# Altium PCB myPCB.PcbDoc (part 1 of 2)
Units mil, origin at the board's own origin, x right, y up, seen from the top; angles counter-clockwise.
Board outline 3914 x 3499.3 mil, 2 copper layers (Top Layer, Bottom Layer); 61 components, 196 nets, 504 pads, 76 vias.
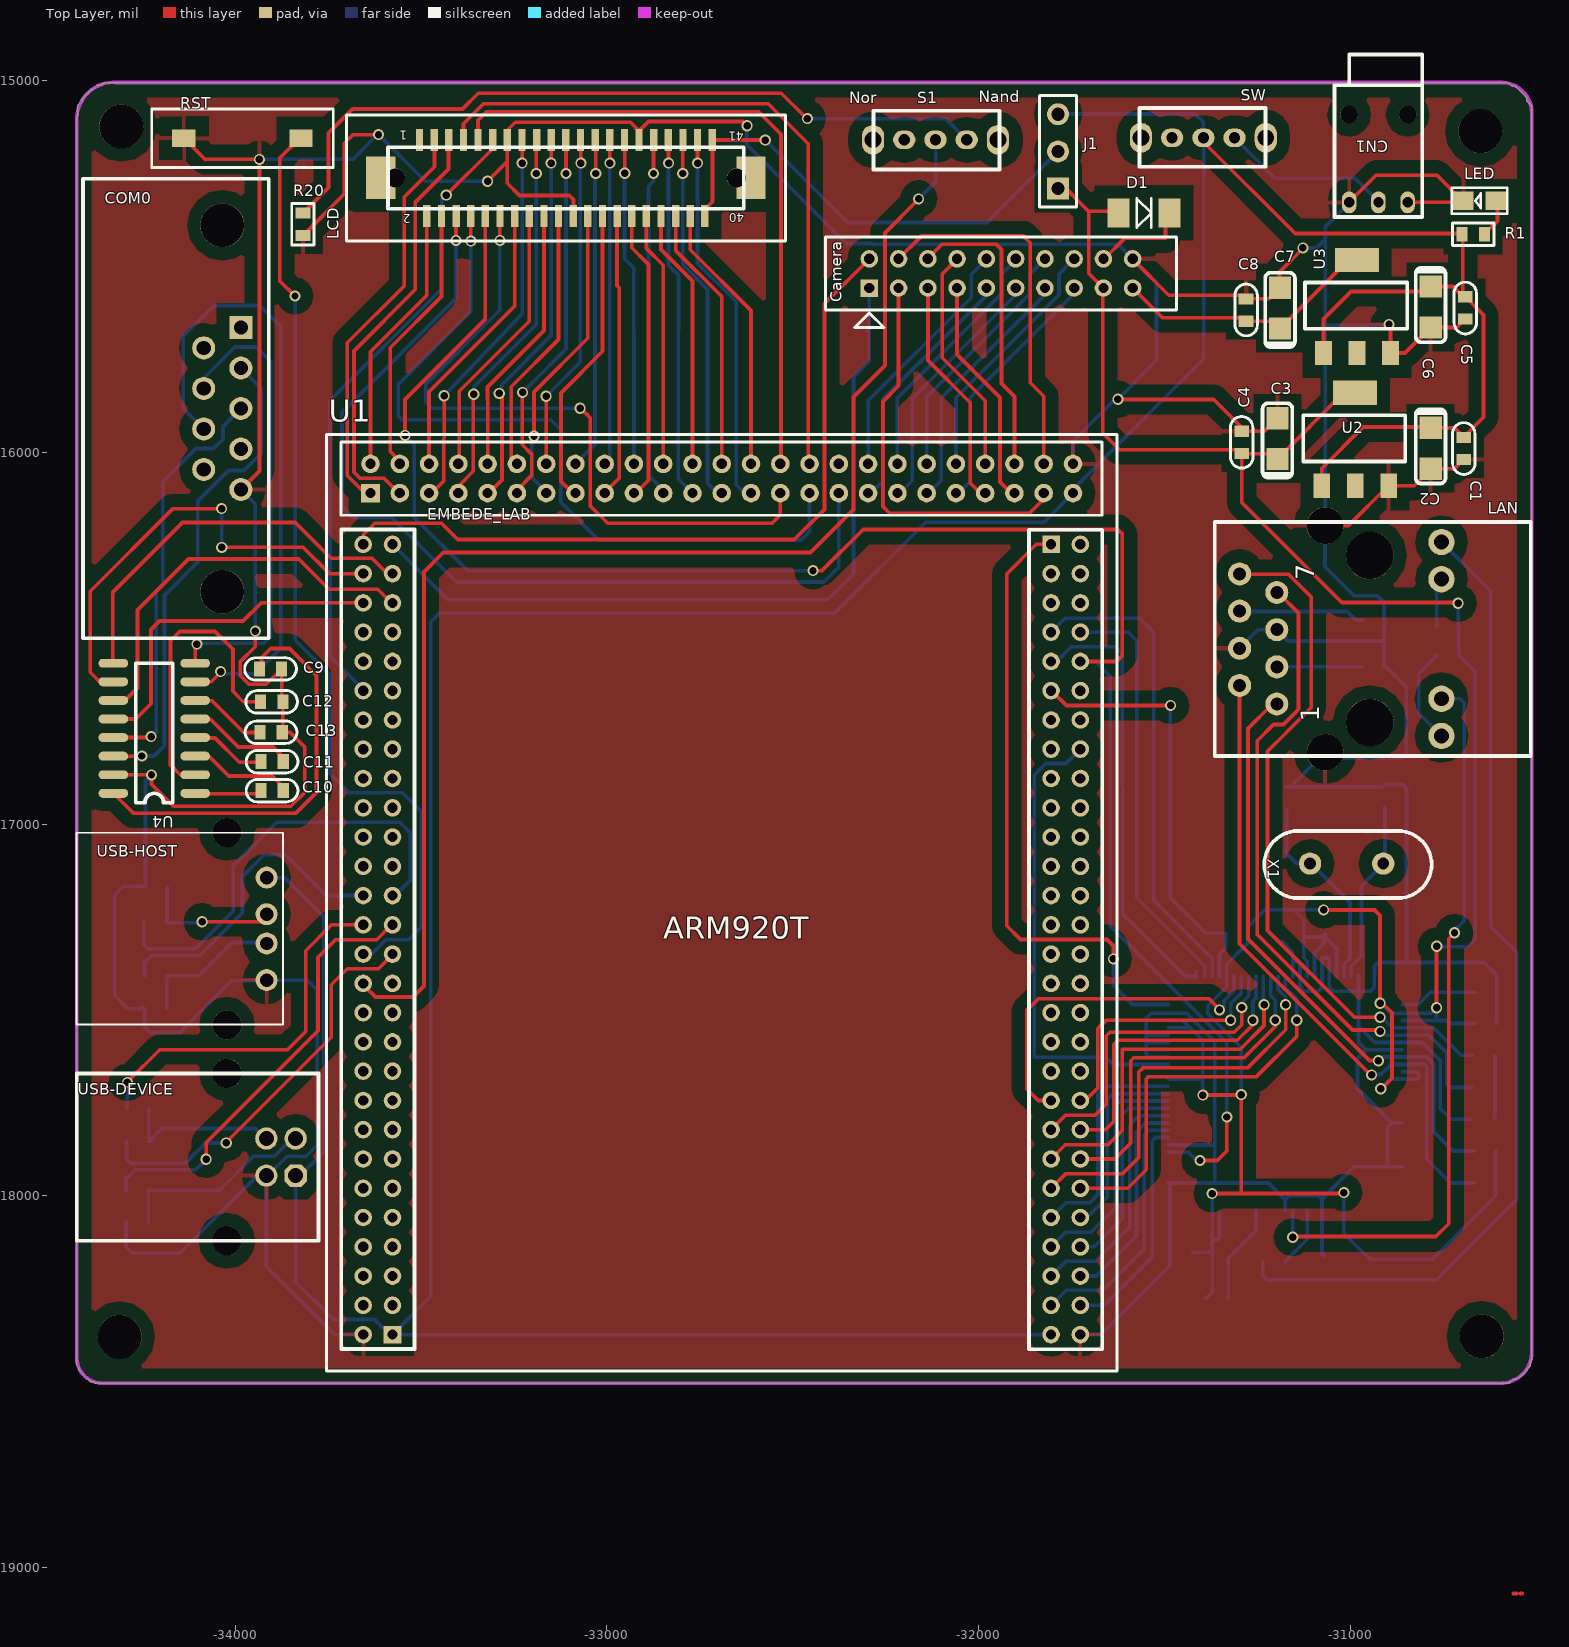
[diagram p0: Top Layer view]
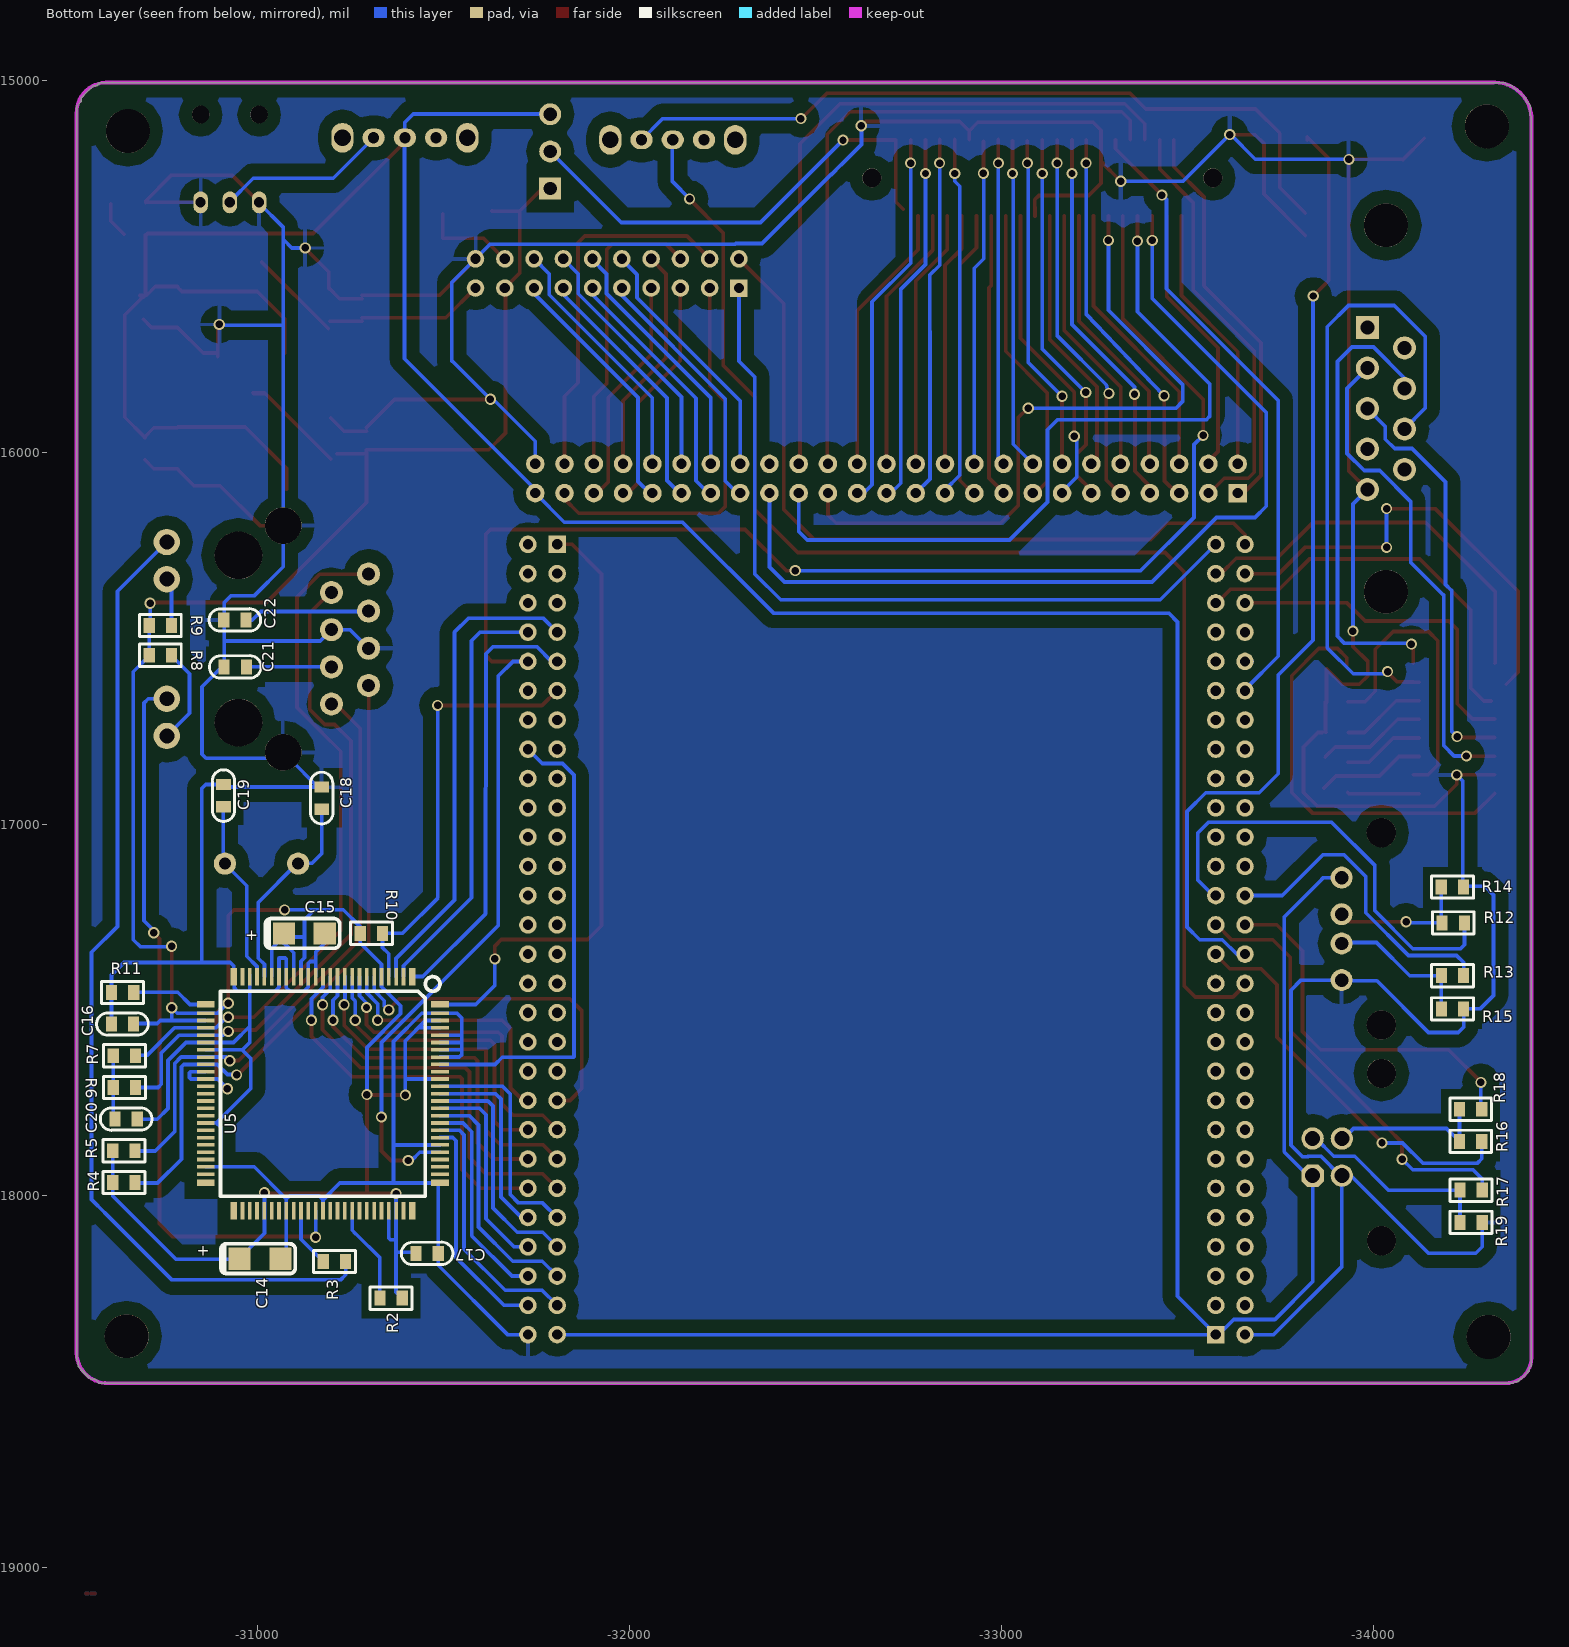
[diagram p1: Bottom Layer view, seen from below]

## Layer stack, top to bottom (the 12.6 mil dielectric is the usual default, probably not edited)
Top Layer: signal copper 1.4
Dielectric: dielectric 12.6, FR-4, Dk 4.8
Bottom Layer: signal copper 1.4

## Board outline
-30598.21,-18504.31 -30572.65,-18504.31 -30571.02,-18502.67 -30562.69,-18494.34 -30553.67,-18494.34 -30551.36,-18494.34 -30545.11,-18488.1 -30524.99,-18467.98 -30524.99,-18467.05 -30516.44,-18458.49 -30516.44,-18446.47 -30512.05,-18442.08 -30512.05,-18422.74 -30512.05,-18388.93 -30512,-18388.88 -30512,-15095.34 -30512,-15068.86 -30518.89,-15061.97 -30525.01,-15055.85 -30525.01,-15050.31 -30525.01,-15045.91 -30539.91,-15031.01 -30556.92,-15013.99 -30566.29,-15013.99 -30574.32,-15005.97 -30585.98,-15005.97 -30608.9,-15005.97 -30609.87,-15005 -30610.4,-15005.53 -34345.49,-15005.53 -34353.67,-15005.53 -34356.4,-15008.26 -34361.19,-15013.05 -34366.96,-15013.05 -34371.71,-15013.05 -34378.24,-15019.58 -34381.56,-15022.9 -34386.55,-15022.9 -34386.55,-15023.61 -34399.18,-15036.24 -34410.98,-15048.04 -34410.98,-15052.67 -34410.98,-15054.75 -34419.3,-15063.07 -34423,-15066.77 -34423,-15083.89 -34423,-15094 -34426,-15097 -34426,-18436.3 -34426,-18456.5 -34420.33,-18462.17 -34420.33,-18469.44 -34409.14,-18480.64 -34389.27,-18500.51 -34380.6,-18500.51 -34376.8,-18504.31 -34356.93,-18504.31 -34282.37,-18504.31 -30598.21,-18504.31

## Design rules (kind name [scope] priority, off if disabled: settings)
Clearance [All] p1: gap=8
ComponentClearance [All] p1: gap=8 collisioncheckmode=3 verticalgap=10 showdistances=FALSE
FabricationTestpoint [(IsPad And (OnTopLayer Or OnBottomLayer))] p1: side=3 testpointundercomponent=TRUE minsize=40 maxsize=100 preferedsize=60 minholesize=0 maxholesize=40 preferedholesize=32 testpointgrid=1 allowsidetop=TRUE allowsidebottom=TRUE usegrid=TRUE gridtolerance=0.01
PolygonConnect [All] p1: connectstyle=Relief reliefconductorwidth=10 reliefentries=4 polygonreliefangle="90 Angle"
RoutingLayers [All] p1: top layer_v5=FALSE bottom layer_v5=FALSE
RoutingVias [All] p1: holewidth=20 width=30 viastyle="Through Hole" minholewidth=20 minwidth=30 maxholewidth=20 maxwidth=30
SMDNeckDown [All] p1: percent=110.000
SilkscreenOverComponentPads [All] p1: minsilkscreentomaskgap=10
SolderMaskExpansion [All] p1: expansion=4
Width [All] p1: maxlimit=12 minlimit=10 preferedwidth=11
24 further rules are at their usual default settings.

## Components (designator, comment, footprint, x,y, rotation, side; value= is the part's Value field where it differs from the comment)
C1 "Cap" 0603A -30696,-15960 r270 top
C2 "Cap2" C3216 -30784,-15934 r180 top
C3 "Cap2" C3216 -31196,-16018 r0 top
C4 "Cap" 0603A -31291,-16003 r90 top
C5 "Cap" 0603A -30692,-15582 r270 top
C6 "Cap2" C3216 -30784,-15554 r180 top
C7 "Cap2" C3216 -31189,-15667 r0 top
C8 "Cap" 0603A -31279,-15647 r90 top
C9 "Cap Semi" 0603A -33934.71,-16584 r0 top
C10 "Cap Semi" 0603A -33871,-16909 r180 top
C11 "Cap Semi" 0603A -33871,-16831 r180 top
C12 "Cap Semi" 0603A -33872,-16670 r180 top
C13 "Cap Semi" 0603A -33873.71,-16752 r180 top
C14 "10uF" C3216 -30950.56,-18169.35 r270 bottom
C15 "10uF" C3216 -31070,-17294.45 r270 bottom
C16 "0.1uF" 0603A -30665.41,-17536.83 r0 bottom
C17 "0.1uF" 0603A -31425.3,-18156.28 r180 bottom
C18 "22p" 0603A -31172.8,-16959.99 r90 bottom
C19 "22p" 0603A -30908.63,-16953.39 r90 bottom
C20 "0.1u" 0603A -30615.54,-17794.85 r180 bottom
C21 "104" 0603A -30968.89,-16576.09 r0 bottom
C22 "104" 0603A -30967.82,-16449.79 r0 bottom
Camera "CON20" IDC20SS -32294,-15558 r180 top locked
CN1 "DC_JACK" DC25 -30924,-15013 r180 top
COM0 "" DB9RA/M -33984.31,-15664.54 r90 top locked
D1 "1N4148" D1206 -31624.53,-15355.89 r0 top
J1 "" HDR1X3 -31786.24,-15290.62 r90 top
LAN "HR911103A" HR911103A -30948,-16501.53 r270 top
LCD "LCD41P" DF9B-41P-1V2 -32651,-15262 r180 top locked
LED "POWER" LED -30609,-15323 r180 top
R1 "500" 0603R -30639,-15413 r180 top
R2 "4.7K" 0603R -31327.63,-18276.01 r180 bottom
R3 "0" 0603R -31236.4,-18176.39 r0 bottom
R4 "50" 0603R -30670.01,-17963.9 r0 bottom
R5 "50" 0603R -30670.01,-17878.7 r0 bottom
R6 "50" 0603R -30610.54,-17709.1 r180 bottom
R7 "50" 0603R -30610.54,-17623.9 r180 bottom
R8 "1K" 0603R -30768,-16545.53 r0 bottom
R9 "1K" 0603R -30768,-16465.53 r0 bottom
R10 "4.7K" 0603R -31274.89,-17294.5 r180 bottom
R11 "6.8K" 0603R -30605.39,-17453.51 r180 bottom
R12 "22" 0603R -34185.16,-17266.39 r180 bottom
R13 "22" 0603R -34183.22,-17408.36 r180 bottom
R14 "15K" 0603R -34183,-17170 r180 bottom
R15 "15K" 0603R -34183.22,-17497.73 r180 bottom
R16 "1.5K" 0603R -34293.02,-17853.34 r0 bottom
R17 "22" 0603R -34294.11,-17984.61 r0 bottom
R18 "22" 0603R -34293.02,-17766.94 r0 bottom
R19 "470K" 0603R -34233.06,-18072.18 r180 bottom
R20 "1K" 0603R -33818.13,-15356.13 r270 top
RST "SW-PB" RST -33980.3,-15154.99 r180 top
S1 "CON5" PCBComponent_1 -32280.01,-15139.29 r0 top
SW "CON5" PCBComponent_1 -31231.36,-15173.89 r180 top
U1 "Micro2440" MICRO2440 -33636.3,-16109.77 r270 top locked
U2 "LM1117" SOT223S -30897,-16090 r90 top
U3 "LM1117" SOT223S -30892,-15733 r90 top
U4 "MAX3232SOP" SSOP16 -34108,-16917 r270 top locked
U5 "DM9000" QFP100 -31415,-17410 r0 bottom
USB-DEVICE "USB Port B type" USB-B -33837.52,-17945.77 r270 top locked
USB-HOST "USB Port A type" USB-A -33915.91,-17143.88 r270 top
X1 "25M" OSC2PR-1 -31108,-17106 r0 top

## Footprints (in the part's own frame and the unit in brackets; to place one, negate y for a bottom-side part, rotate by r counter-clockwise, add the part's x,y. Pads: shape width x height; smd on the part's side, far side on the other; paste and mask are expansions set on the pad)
0603A [mil]
  rect 30x40 smd: 1(-0.26,1.21) 2(59.74,1.21)
  silkscreen extent -40,-29 99,31
0603R [mil]
  rect 30x40 smd: 1(0.47,0.42) 2(60.47,0.42)
  silkscreen extent -26,-30 87,30
C3216 [mil]
  rect 60x60 smd: 1(0,0) 2(0,110)
  silkscreen extent -40,-50 40,150
D1206 [mm]
  rect 1.5x2 smd: 1(0.015,-0.01) 2(3.515,-0.01)
  silkscreen extent 1.26,-1.01 2.26,0.99
DB9RA/M [mil]
  rect 62x62 hole 38: 1(0.38,0.31)
  round 62 hole 38: 2(-108.62,0.31) 3(-217.62,0.31) 4(-326.62,0.31) 5(-435.62,0.31) 6(-54.62,100.31) 7(-163.62,100.31) 8(-272.62,100.31) 9(-381.62,100.31)
  round 118.11 hole 118.11: ""(-710.62,50.31) ""(275.38,50.31)
  silkscreen extent -836,-75 400,425
DC25 [mm]
  oval 1x1.5 hole 0.7: 1(2.012,7.989) 2(0.012,7.989) 3(-1.988,7.989)
  round 1.2 hole 1.2: A(-1.988,1.989) B(2.012,1.989)
  silkscreen extent -2.99,-2.11 3.01,8.99
DF9B-41P-1V2 [mm]
  rect 0.5x1.5 smd: 1(21.667,-2.605) 2(21.167,2.595) 3(20.667,-2.605) 4(20.167,2.595) 5(19.667,-2.605) 6(19.167,2.595) 7(18.667,-2.605) 8(18.167,2.595) 9(17.667,-2.605) 10(17.167,2.595) 11(16.667,-2.605) 12(16.167,2.595) 13(15.667,-2.605) 14(15.167,2.595) 15(14.667,-2.605) 16(14.167,2.595) 17(13.667,-2.605) 18(13.167,2.595) 19(12.667,-2.605) 20(12.167,2.595) 21(11.667,-2.605) 22(11.167,2.595) 23(10.667,-2.605) 24(10.167,2.595) 25(9.667,-2.605) 26(9.167,2.595) 27(8.667,-2.605) 28(8.167,2.595) 29(7.667,-2.605) 30(7.167,2.595) 31(6.667,-2.605) 32(6.167,2.595) 33(5.667,-2.605) 34(5.167,2.595) 35(4.667,-2.605) 36(4.167,2.595) 37(3.667,-2.605) 38(3.167,2.595) 39(2.667,-2.605) 40(2.167,2.595) 41(1.667,-2.605)
  round 1.3 hole 1.3: A(0.017,-0.005) B(23.317,-0.005)
  rect 2x2.9 smd: C(-0.983,-0.005) D(24.317,-0.005)
  silkscreen extent -3.33,-4.31 26.67,4.3
HDR1X3 [mm] "Connector; Header; 3 Position"
  rect 1.5x1.5 hole 0.9: 1(0,0)
  round 1.5 hole 0.9: 2(2.54,0) 3(5.08,0)
  silkscreen extent -1.27,-1.27 6.35,1.27
HR911103A [mil]
  round 62 hole 35: 1(175.67,-249.76) 2(125.67,-349.76) 3(75.67,-249.76) 4(25.67,-349.76) 5(-24.33,-249.76) 6(-74.33,-349.76) 7(-124.33,-249.76) 8(-174.33,-349.76)
  round 70.87 hole 40.16: 9(261.5,193.16) 10(161.5,193.16) 11(-160.16,193.16) 12(-260.16,193.16)
  round 98.42 hole 98.43: A(305.59,-119.83) B(-304.25,-119.83)
  round 127.95 hole 127.95: C(-224.33,0.24) D(225.67,0.24)
  silkscreen extent -314,-416 316,433
IDC20SS [mm]
  rect 1.2x1.2 hole 0.7: 1(0.002,0.003)
  round 1.2 hole 0.7: 2(0.002,-1.997) 3(-1.998,0.003) 4(-1.998,-1.997) 5(-3.998,0.003) 6(-3.998,-1.997) 7(-5.998,0.003) 8(-5.998,-1.997) 9(-7.998,0.003) 10(-7.998,-1.997) 11(-9.998,0.003) 12(-9.998,-1.997) 13(-11.998,0.003) 14(-11.998,-1.997) 15(-13.998,0.003) 16(-13.998,-1.997) 17(-15.998,0.003) 18(-15.998,-1.997) 19(-17.998,0.003) 20(-17.998,-1.997)
  silkscreen extent -21,-3.5 3,2.7
LED [mil]
  rect 55.12x50 smd: 1(-0.13,0.5) 2(86.87,0.5)
  silkscreen extent -32,-35 118,36
MICRO2440 [mm]
  rect 1.2x1.2 hole 0.7: PA1(57.501,1.512) PC1(3.501,46.512)
  round 1.2 hole 0.7: PA2(57.501,-0.488) PA3(55.501,1.512) PA4(55.501,-0.488) PA5(53.501,1.512) PA6(53.501,-0.488) PA7(51.501,1.512) PA8(51.501,-0.488) PA9(49.501,1.512) PA10(49.501,-0.488) PA11(47.501,1.512) PA12(47.501,-0.488) PA13(45.501,1.512) PA14(45.501,-0.488) PA15(43.501,1.512) PA16(43.501,-0.488) PA17(41.501,1.512) PA18(41.501,-0.488) PA19(39.501,1.512) PA20(39.501,-0.488) PA21(37.501,1.512) PA22(37.501,-0.488) PA23(35.501,1.512) PA24(35.501,-0.488) PA25(33.501,1.512) PA26(33.501,-0.488) PA27(31.501,1.512) PA28(31.501,-0.488) PA29(29.501,1.512) PA30(29.501,-0.488) PA31(27.501,1.512) PA32(27.501,-0.488) PA33(25.501,1.512) PA34(25.501,-0.488) PA35(23.501,1.512) PA36(23.501,-0.488) PA37(21.501,1.512) PA38(21.501,-0.488) PA39(19.501,1.512) PA40(19.501,-0.488) PA41(17.501,1.512) PA42(17.501,-0.488) PA43(15.501,1.512) PA44(15.501,-0.488) PA45(13.501,1.512) PA46(13.501,-0.488) PA47(11.501,1.512) PA48(11.501,-0.488) PA49(9.501,1.512) PA50(9.501,-0.488) PA51(7.501,1.512) PA52(7.501,-0.488) PA53(5.501,1.512) PA54(5.501,-0.488) PA55(3.501,1.512) PA56(3.501,-0.488) PC2(3.501,48.512) PC3(5.501,46.512) PC4(5.501,48.512) PC5(7.501,46.512) PC6(7.501,48.512) PC7(9.501,46.512) PC8(9.501,48.512) PC9(11.501,46.512) PC10(11.501,48.512) PC11(13.501,46.512) PC12(13.501,48.512) PC13(15.501,46.512) PC14(15.501,48.512) PC15(17.501,46.512) PC16(17.501,48.512) PC17(19.501,46.512) PC18(19.501,48.512) PC19(21.501,46.512) PC20(21.501,48.512) PC21(23.501,46.512) PC22(23.501,48.512) PC23(25.501,46.512) PC24(25.501,48.512) PC25(27.501,46.512) PC26(27.501,48.512) PC27(29.501,46.512) PC28(29.501,48.512) PC29(31.501,46.512) PC30(31.501,48.512) PC31(33.501,46.512) PC32(33.501,48.512) PC33(35.501,46.512) PC34(35.501,48.512) PC35(37.501,46.512) PC36(37.501,48.512) PC37(39.501,46.512) PC38(39.501,48.512) PC39(41.501,46.512) PC40(41.501,48.512) PC41(43.501,46.512) PC42(43.501,48.512) PC43(45.501,46.512) PC44(45.501,48.512) PC45(47.501,46.512) PC46(47.501,48.512) PC47(49.501,46.512) PC48(49.501,48.512) PC49(51.501,46.512) PC50(51.501,48.512) PC51(53.501,46.512) PC52(53.501,48.512) PC53(55.501,46.512) PC54(55.501,48.512) PC55(57.501,46.512) PC56(57.501,48.512)
  rect 1.27x1.27 hole 0.7: PB1(0.001,0.012)
  round 1.27 hole 0.7: PB2(-1.999,0.012) PB3(0.001,2.012) PB4(-1.999,2.012) PB5(0.001,4.012) PB6(-1.999,4.012) PB7(0.001,6.012) PB8(-1.999,6.012) PB9(0.001,8.012) PB10(-1.999,8.012) PB11(0.001,10.012) PB12(-1.999,10.012) PB13(0.001,12.012) PB14(-1.999,12.012) PB15(0.001,14.012) PB16(-1.999,14.012) PB17(0.001,16.012) PB18(-1.999,16.012) PB19(0.001,18.012) PB20(-1.999,18.012) PB21(0.001,20.012) PB22(-1.999,20.012) PB23(0.001,22.012) PB24(-1.999,22.012) PB25(0.001,24.012) PB26(-1.999,24.012) PB27(0.001,26.012) PB28(-1.999,26.012) PB29(0.001,28.012) PB30(-1.999,28.012) PB31(0.001,30.012) PB32(-1.999,30.012) PB33(0.001,32.012) PB34(-1.999,32.012) PB35(0.001,34.012) PB36(-1.999,34.012) PB37(0.001,36.012) PB38(-1.999,36.012) PB39(0.001,38.012) PB40(-1.999,38.012) PB41(0.001,40.012) PB42(-1.999,40.012) PB43(0.001,42.012) PB44(-1.999,42.012) PB45(0.001,44.012) PB46(-1.999,44.012) PB47(0.001,46.012) PB48(-1.999,46.012) PB49(0.001,48.012) PB50(-1.999,48.012)
  silkscreen extent -4,-2.99 60,51.01
OSC2PR-1 [mil]
  round 60 hole 32: 1(-0.31,-0.47) 2(196.69,-0.47)
  silkscreen extent -123,-93 327,87
PCBComponent_1 [mil]
  oval 60x80 hole 45: 1(-4,-20) 5(332,-20)
  oval 60x50 hole 30: 2(80,-20) 3(164,-20) 4(248,-20)
  silkscreen extent -3,-100 336,58
QFP100 [mm]
  rect 0.45x1.2 smd: 1(-0.002,0.012) 25(12.198,0.012) 51(12.198,16.012) 75(-0.002,16.012)
  rect 0.25x1.2 smd: 2(0.598,0.012) 3(1.098,0.012) 4(1.598,0.012) 5(2.098,0.012) 6(2.598,0.012) 7(3.098,0.012) 8(3.598,0.012) 9(4.098,0.012) 10(4.598,0.012) 11(5.098,0.012) 12(5.598,0.012) 13(6.098,0.012) 14(6.598,0.012) 15(7.098,0.012) 16(7.598,0.012) 17(8.098,0.012) 18(8.598,0.012) 19(9.098,0.012) 20(9.598,0.012) 21(10.098,0.012) 22(10.598,0.012) 23(11.098,0.012) 24(11.598,0.012) 52(11.598,16.012) 53(11.098,16.012) 54(10.598,16.012) 55(10.098,16.012) 56(9.598,16.012) 57(9.098,16.012) 58(8.598,16.012) 59(8.098,16.012) 60(7.598,16.012) 61(7.098,16.012) 62(6.598,16.012) 63(6.098,16.012) 64(5.598,16.012) 65(5.098,16.012) 66(4.598,16.012) 67(4.098,16.012) 68(3.598,16.012) 69(3.098,16.012) 70(2.598,16.012) 71(2.098,16.012) 72(1.598,16.012) 73(1.098,16.012) 74(0.598,16.012)
  rect 1.2x0.45 smd: 26(14.098,1.912) 50(14.098,14.112) 76(-1.902,14.112) 100(-1.902,1.912)
  rect 1.2x0.25 smd: 27(14.098,2.512) 28(14.098,3.012) 29(14.098,3.512) 30(14.098,4.012) 31(14.098,4.512) 32(14.098,5.012) 33(14.098,5.512) 34(14.098,6.012) 35(14.098,6.512) 36(14.098,7.012) 37(14.098,7.512) 38(14.098,8.012) 39(14.098,8.512) 40(14.098,9.012) 41(14.098,9.512) 42(14.098,10.012) 43(14.098,10.512) 44(14.098,11.012) 45(14.098,11.512) 46(14.098,12.012) 47(14.098,12.512) 48(14.098,13.012) 49(14.098,13.512) 77(-1.902,13.512) 78(-1.902,13.012) 79(-1.902,12.512) 80(-1.902,12.012) 81(-1.902,11.512) 82(-1.902,11.012) 83(-1.902,10.512) 84(-1.902,10.012) 85(-1.902,9.512) 86(-1.902,9.012) 87(-1.902,8.512) 88(-1.902,8.012) 89(-1.902,7.512) 90(-1.902,7.012) 91(-1.902,6.512) 92(-1.902,6.012) 93(-1.902,5.512) 94(-1.902,5.012) 95(-1.902,4.512) 96(-1.902,4.012) 97(-1.902,3.512) 98(-1.902,3.012) 99(-1.902,2.512)
  silkscreen extent -1.9,0.01 13.1,15.01
RST [mm]
  rect 1.6x1.2 smd: 1(-4,0) 2(4,0)
  silkscreen extent -6.2,-2 6.2,2
SOT223S [mil]
  rect 65x45 smd: 1(0,0) 2(0,90) 3(0,180)
  rect 65x118 smd: 4(250,90)
  silkscreen extent 65,-45 190,230
SSOP16 [mil]
  oval 24x80 smd: 1(0.44,0.31) 2(-49.56,0.31) 3(-99.56,0.31) 4(-149.56,0.31) 5(-199.56,0.31) 6(-249.56,0.31) 7(-299.56,0.31) 8(-349.56,0.31) 9(-349.56,-219.69) 10(-299.56,-219.69) 11(-249.56,-219.69) 12(-199.56,-219.69) 13(-149.56,-219.69) 14(-99.56,-219.69) 15(-49.56,-219.69) 16(0.44,-219.69)
  silkscreen extent -350,-160 25,-60
USB-A [mm]
  round 1.5 hole 0.92: 1(0.009,0.013) 2(2.509,0.013) 3(4.509,0.013) 4(7.009,0.013)
  round 2 hole 2: 5(10.079,-2.697) 6(-3.061,-2.697)
  silkscreen extent -3.06,-12.98 10.04,1.12
USB-B [mil]
  oct 60x60 hole 40: 1(0.24,0.17)
  round 60 hole 40: 2(-99.76,0.17) 3(-99.76,-78.57) 4(0.24,-78.57)
  round 78.74 hole 78.74: 5(175.24,-184.87) 6(-274.76,-184.87)
  silkscreen extent -275,-589 175,61

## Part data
C1 C2 C3 C4 C5 C6 C7 C8: "Capacitor"
C9 C10 C11 C12 C13: "Capacitor (Semiconductor SIM Model)"
C14 C15: library part ELECTRO1
C16 C17 C18 C19 C20: library part CAP
C21 C22: library part "CAP NP_0"
Camera S1 SW: "Connector"
CN1: library part CON3
COM0: library part "CONNECTOR DB9"
D1: library part DIODE
J1: library part "Header 3", "Header, 3-Pin"
LED: library part LED3, "Typical BLUE SiC LED"
R1 R8 R9 R20: library part RES1
R2 R3 R4 R5 R6 R7 R11: library part RES2
R10: library part R_0
R12 R13 R14 R15 R16 R17 R18 R19: library part RESISTOR_2
RST: "Switch"
U1 U4: library part Component_1
USB-DEVICE USB-HOST: library part USBPORT
X1: library part CRYSTAL

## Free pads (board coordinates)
  round 118.11 hole 118.11: 0(-34310.8,-18379.6) 1(-34306,-15123) 2(-30650,-15136) 3(-30646.71,-18377.93)

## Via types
v1: diameter 30, hole 20, Top Layer to Bottom Layer, 75 vias
v2: diameter 30, hole 20, Top Layer to Bottom Layer, tented top, 1 vias

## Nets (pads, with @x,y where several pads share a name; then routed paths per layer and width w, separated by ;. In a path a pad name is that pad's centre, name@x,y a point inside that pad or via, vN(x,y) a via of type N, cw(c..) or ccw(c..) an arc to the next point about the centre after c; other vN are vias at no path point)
AIN1: U1.PA36
AIN2: U1.PA33
ATN0: U1.PA35
CAM_HREF: Camera.6 U1.PB46 | length 813
  Top Layer w10: Camera.6@-32138,-15480 -32098,-15440 -31953.23,-15440 -31938.54,-15454.69 -31938.54,-15814.9 -31903.56,-15849.89 U1.PB46@-31903.56,-16031.09
CAM_PCLK: Camera.8 U1.PB44 | length 615.6
  Top Layer w10: Camera.8@-32058,-15480 -32098,-15520 -32098,-15745.36 -31982.3,-15861.06 U1.PB44@-31982.3,-16031.09
CAM_VSYNC: Camera.7 U1.PB45 | length 621.1
  Top Layer w10: Camera.7@-32058,-15558 -32058,-15558.1 -32058,-15737.11 -31942.23,-15852.88 -31942.23,-16080.15 -31912.56,-16109.83 U1.PB45@-31903.56,-16109.83
CAMCLK: Camera.5 U1.PB43 | length 623.2
  Top Layer w10: Camera.5@-32136,-15558 -32136,-15558.1 -32136,-15753.2 -32022.57,-15866.64 -32022.57,-16082.75 -31995.49,-16109.83 U1.PB43@-31982.3,-16109.83
CAMDATA0: Camera.16 U1.PB42 | length 682.4
  Bottom Layer w10: U1.PB42@-32061.04,-16031.09 -32061.04,-15853.04 -31784,-15576 -31784,-15520 Camera.16@-31744,-15480
CAMDATA1: Camera.15 U1.PB41 | length 687.1
  Bottom Layer w10: U1.PB41@-32061.04,-16109.83 -32054.24,-16109.83 -32022.74,-16078.32 -32022.74,-15852.74 -31744,-15574 Camera.15@-31744,-15558
CAMDATA2: Camera.14 U1.PB40 | length 685.5
  Bottom Layer w10: U1.PB40@-32139.78,-16031.09 -32139.78,-15851.34 -31862,-15573.56 -31862,-15520 Camera.14@-31820,-15478
CAMDATA3: Camera.13 U1.PB39 | length 687.5
  Bottom Layer w10: U1.PB39@-32139.78,-16109.83 -32133.85,-16109.83 -32100.24,-16076.22 -32100.24,-15853.55 -31978.4,-15731.7 ; -31977.7,-15731.7 -31820,-15574 Camera.13@-31820,-15558
CAMDATA4: Camera.12 U1.PB38 | length 683.8
  Bottom Layer w10: U1.PB38@-32218.52,-16031.09 -32218.52,-15853.64 -31938,-15573.12 -31938,-15520 Camera.12@-31898,-15480
CAMDATA5: Camera.11 U1.PB37 | length 705.5
  Bottom Layer w10: U1.PB37@-32218.52,-16109.83 -32211.67,-16109.83 -32178.43,-16076.59 -32178.43,-15854.37 -31900.37,-15576.31 Camera.11@-31900.37,-15558.1 ; Camera.11@-31898,-15576 Camera.11@-31898,-15558
CAMDATA6: Camera.10 U1.PB36 | length 683.3
  Bottom Layer w10: U1.PB36@-32297.26,-16031.09 -32297.26,-15861.36 -32020,-15584.1 -32020,-15522 Camera.10@-31978,-15480
CAMDATA7: Camera.9 U1.PB35 | length 688
  Bottom Layer w10: U1.PB35@-32297.26,-16109.83 -32289.62,-16109.83 -32257.08,-16077.29 -32257.08,-15856.4 -31979.11,-15578.43 Camera.9@-31979.11,-15558.1
CAMRST: Camera.4 U1.PB48 | length 1010
  Top Layer w10: Camera.4@-32216,-15480 -32154,-15418 -31879.4,-15418 -31861.3,-15436.1 -31861.3,-15812.78 -31824.82,-15849.26 U1.PB48@-31824.82,-16031.09 ; Camera.4@-32212,-15478 Camera.4@-32212,-15466
CDCLK: U1.PA42
DN0: R12.2 U1.PA31 | length 1203.7
  Bottom Layer w10: R12.2@-34246.06,-17259.88 -34246.06,-17324.95 -34235.47,-17335.54 -34106.78,-17335.54 -34004.81,-17233.56 -34004.81,-17111.69 -33888.16,-16995.03 -33557.49,-16995.03 -33528.62,-17023.9 -33528.62,-17150.9 -33570.23,-17192.5 U1.PA31@-33576.79,-17192.5
DN1: R17.1 U1.PA29 | length 1173.8
  Top Layer w10: v1(-34078,-17902) -34078,-17857.06 -34037.87,-17816.93 -34037.72,-17817.08 -34037.72,-17816.79 -33777.26,-17556.32 -33777.26,-17358.3 -33730.3,-17311.34 -33619.29,-17311.34 -33579.19,-17271.24 U1.PA29@-33576.79,-17271.24
  Bottom Layer w10: R17.1@-34293.63,-17985.03 -34293.63,-17955.17 -34268.73,-17930.27 -34106.44,-17930.27 v1@-34077.19,-17901.03
DP0: R13.2 U1.PA32 | length 846
  Bottom Layer w10: R13.2@-34243.69,-17407.94 -34243.69,-17372.76 -34224.47,-17353.54 -34095.06,-17353.54 -33980.07,-17238.55 -33980.07,-17141.08 -33921.78,-17082.79 -33865.16,-17082.79 -33755.45,-17192.5 U1.PA32@-33655.53,-17192.5
DP1: R18.1 U1.PA30 | length 1004.5
  Top Layer w10: v1@-34289,-17693 -34203,-17607 -33859,-17607 -33810,-17558 -33810,-17340.69 -33740.56,-17271.24 U1.PA30@-33655.53,-17271.24
  Bottom Layer w10: R18.1@-34290,-17764 v1(-34290,-17695)
EINT0: U1.PA18
EINT1: U1.PA17
EINT2: U1.PA16
EINT3: U1.PA15
EINT4: U1.PA14
EINT5: U1.PA13
EINT6: U1.PA12
EINT7: U1.PC1 U5.100 | length 1682.4
  Top Layer w10: U1.PC1@-31805.13,-16247.62 -31845.01,-16247.62 -31924.52,-16327.13 -31924.52,-17273.46 -31887.28,-17310.7 -31654.82,-17310.7 -31637.43,-17328.1 v1(-31637.43,-17362.8)
  Bottom Layer w10: v1@-31637.06,-17363.17 -31637.06,-17434.17 -31585.95,-17485.28 U5.100@-31489.87,-17485.28
EINT8: U1.PA11
EINT9: U1.PC2
EINT11: U1.PA10
EINT13: U1.PA9
EINT14: U1.PA8
EINT15: U1.PA7
EINT16: U1.PA6
EINT17: U1.PA5
EINT18: U1.PA4
EINT19: U1.PA3
EINT20: Camera.3 U1.PB47 | length 1076.8
  Top Layer w10: Camera.3@-32215.33,-15558.1 -32215.33,-15821.21 -32257.13,-15863 -32257.13,-16146.01 -32239.01,-16164.12 -31863.19,-16164.12 -31824.82,-16125.75 U1.PB47@-31824.82,-16109.83
GND: C1.2 C2.2 C3.2 C4.2 C5.2 C6.2 C7.2 C8.2 C9.2 C12.1 C13.1 C14.2 C15.2 C16.2 C17.2 C18.2 C19.2 C20.2 C21.2 C22.2 Camera.20 CN1.1 CN1.3 COM0.5 LAN.4 LAN.5 LAN.A LAN.B LCD.13 LCD.22 LCD.31 LED.2 R11.1 R14.2 R15.2 R19.2 R20.2 RST.2 U1.PA2 U1.PB50 U1.PC56 U2.1 U3.1 U4.15 U5.14 U5.15 U5.18 U5.19 U5.23 U5.25 U5.31 U5.32 U5.42 U5.48 U5.58 U5.63 U5.76 U5.81 U5.93 U5.94 U5.95 U5.96 U5.99 USB-DEVICE.4 USB-HOST.4 | length 20566.3
  Top Layer w10: U4.15@-34327.69,-16867.44 v1@-34229.44,-16867.44 ; v1(-34225,-16868) -34225,-16893 -34165.6,-16952.4 -33850.4,-16952.4 -33813,-16915 -33813,-16793 -33852,-16754 C13.1@-33863,-16754 ; RST.2@-34137.78,-15154.99 -34080.57,-15212.2 v1(-33934.79,-15212) -33934.79,-16050.32 COM0.5@-33984.63,-16100.16 ; v1(-33945.74,-16481.16) -33945.74,-16522.81 -33986,-16563.07 -33986,-16601 -33963,-16624 -33916.19,-16624 C9.2@-33874.97,-16582.79 -33874.97,-16673.03 C12.1@-33871.74,-16676.26 ; C13.1@-33873.45,-16753.21 -33871.74,-16753.21 C12.1@-33871.74,-16671.21 ; R20.2@-33817.71,-15416.6 -33706.36,-15305.25 -33706.36,-15168.81 -33683.16,-15145.61 v1@-33616.56,-15145.61 ; v1(-33321.07,-15270.89) -33268,-15217.83 ; LCD.22@-33090.65,-15364.16 LCD.22@-33090.65,-15343.35 ; LCD.22@-33090.65,-15341.35 -33089.98,-15340.67 -33089.98,-15320.21 -33101.04,-15309.15 -33234.85,-15309.15 -33268,-15276 -33268,-15133.44 -33246.56,-15112 -32936.79,-15112 -32913.49,-15135.3 LCD.31@-32913.49,-15159.43 ; LCD.31@-32913.49,-15135.46 -32888.03,-15110 -32675.88,-15110 ; -32674.83,-15109.91 -32635.25,-15109.91 v1@-32623.98,-15121.18 ; v1@-31624,-15858 -31367.47,-15858 C4.2@-31292.21,-15933.26 ; Camera.20@-31586,-15480 -31488.74,-15577.26 C8.2@-31280.21,-15577.26 ; C4.2@-31292.21,-15943.26 -31231.26,-15943.26 C3.2@-31196,-15908 ; C8.2@-31280.21,-15587.26 -31220.26,-15587.26 C7.2@-31191,-15558 ; C7.2@-31190.29,-15559.64 -31190.29,-15514.82 v1@-31128.08,-15452.61 ; LAN.B@-31067.83,-16197.28 -31005.28,-16197.28 U2.1@-30898,-16090 ; CN1.1@-31003.22,-15327.53 -30930,-15254.31 -30767.69,-15254.31 LED.2@-30698,-15324 ; U2.1@-30897,-16090 -30828,-16090 C2.2@-30782,-16044 ; v1(-30896,-15656) -30892,-15660 U3.1@-30892,-15742 ; U3.1@-30892,-15733 -30853,-15733 C6.2@-30784,-15664 -30714,-15664 C5.2@-30692,-15642 ; CN1.3@-30845.74,-15327.53 -30698.47,-15327.53 LED.2@-30698,-15328 ; C2.2@-30784,-16044 -30720,-16044 C1.2@-30696,-16020
  Bottom Layer w10: R19.2@-34293.53,-18071.76 -34293.53,-18137.33 -34276.41,-18154.45 -34149.03,-18154.45 -33941.15,-17946.58 USB-DEVICE.4@-33913.73,-17946.58 ; R15.2@-34247.35,-17493.66 R15.2@-34243.69,-17497.31 ; v1(-34225,-16868) -34241,-16884 -34241,-17167.68 -34300.37,-17167.68 -34323.71,-17191.02 -34323.71,-17461.59 -34287.99,-17497.31 R15.2@-34243.69,-17497.31 ; COM0.5@-33984.63,-16100.16 -33946,-16138.79 -33946,-16480.9 v1(-33945.74,-16481.16) ; v1@-33934.79,-15213.92 -33932.23,-15211.36 -33683.17,-15211.36 v1@-33614.85,-15143.05 ; USB-HOST.4@-33916.75,-17419.62 -33916.44,-17419.93 -33806.02,-17419.93 -33779,-17446.95 -33779,-17506 -33779,-17864 -33810,-17895 -33825,-17895 ; USB-DEVICE.4@-33916.09,-17946.02 -33916.09,-18190.18 -33732.66,-18373.61 U1.PA2@-33655.53,-18373.61 ; USB-HOST.4@-33915.38,-17419.81 -33912.12,-17421.65 -34010.19,-17421.65 -34149.19,-17560.66 -34229.25,-17560.66 -34243.69,-17546.22 R15.2@-34243.69,-17497.31 ; USB-DEVICE.4@-33914.05,-17948.05 -33860,-17894 -33824,-17894 ; v1@-33615.6,-15145.49 v1@-33614.4,-15145.49 ; v1@-33613.29,-15146.08 -33488.47,-15270.89 v1(-33321.07,-15270.89) ; v1@-32623.6,-15121.36 -32623.6,-15172.08 -32582.18,-15213.51 -32581.99,-15213.51 -32580.44,-15215.06 -32580.44,-15215.19 -32569.74,-15225.89 -32569.57,-15225.89 -32543.08,-15252.39 -32541.97,-15252.39 -32356.27,-15438.09 -32285.91,-15438.09 -32284,-15440 -31624.77,-15440 Camera.20@-31585.41,-15479.36 ; U1.PB50@-31746.08,-16031.09 -31746.08,-15970.34 -31633.17,-15857.43 v1(-31625.36,-15857.43) -31522.69,-15754.75 ; U1.PC56@-31726.39,-18373.61 -31671.52,-18373.61 -31485.04,-18187.13 -31485.04,-17969.63 -31488.16,-17966.51 U5.76@-31489.87,-17965.59 -31220,-17966 -31174.91,-18011.09 U5.63@-31174.91,-18040.39 ; Camera.20@-31586.69,-15478.04 -31521.59,-15543.15 -31521.59,-15754.75 ; Camera.20@-31584.39,-15480.39 Camera.20@-31584,-15480 ; -31548.51,-17587.64 U5.95@-31489.87,-17587.64 ; -31548.27,-17567.95 U5.96@-31489.87,-17567.95 ; -31548.17,-17607.32 U5.94@-31489.87,-17607.32 ; U5.81@-31489.87,-17863.23 -31365.96,-17863.23 -31364.78,-17864.4 ; U5.93@-31489.87,-17627.01 -31541.81,-17627.01 -31548.72,-17620.1 -31548.72,-17522.3 -31535.31,-17508.9 U5.99@-31489.87,-17508.9 -31440.87,-17508.9 -31364.78,-17584.99 -31364.78,-17864.4 ; -31364.78,-17965.11 -31364.78,-17864.4 ; LAN.4@-31297.76,-16527.2 -31248.09,-16477.53 LAN.5@-31198,-16477.53 ; LAN.5@-31197.76,-16477.2 -31167.43,-16507.53 -30909.64,-16507.53 -30909.15,-16507.05 ; C15.2@-31184,-17316 -31155.22,-17344.78 U5.14@-31155.22,-17410.47 ; -31174.91,-18010.91 -31164,-18000 -31086,-18000 -31076.48,-18009.52 -31076.48,-18156.65 C14.2@-31072.1,-18161.03 ; C18.2@-31171.58,-16900.25 -30914.02,-16900.25 C19.2@-30907.42,-16893.65 -30859.73,-16893.65 -30848.91,-16904.47 -30848.91,-17369.51 -30851.85,-17372.45 ; C18.2@-31160.97,-16900.25 -31084.01,-16823.3 -30860.68,-16823.3 -30849.66,-16812.27 -30849.66,-16630.46 -30902.81,-16577.31 C21.2@-30909.15,-16577.31 -30909.15,-16466.47 C22.2@-30911.29,-16464.33 ; -31155.22,-17369.74 -31140.7,-17369.74 -31135.54,-17374.9 -31135.54,-17438.46 -31124,-17450 -31086,-17450 -31076.48,-17440.48 U5.18@-31076.48,-17410.47 -31076.48,-17363.34 -31073.8,-17360.66 -31057.08,-17360.66 -31056.8,-17360.94 -31056.8,-17439.2 -31046,-17450 -30946,-17450 -30936,-17440 U5.25@-30936,-17410 ; v1(-31127.41,-15450.18) -31091.17,-15450.18 -31069.39,-15428.4 ; -31076.48,-18008.48 -30990.28,-17922.28 U5.48@-30859.94,-17922.28 ; LAN.B@-31068,-16197.53 -31068,-16308 -30989.72,-16386.28 -30927.09,-16386.28 -30909.53,-16403.83 C22.2@-30909.53,-16452.08 ; LAN.B@-31067.83,-16197.28 -31067.83,-15393.83 CN1.1@-31002.37,-15328.37 ; -31067.83,-15658 v1@-30898,-15658 ; -30978.06,-17450 U5.23@-30978.06,-17410.47 ; -30978,-17544 -30934.36,-17587.64 U5.31@-30859.94,-17587.64 -30806.36,-17587.64 -30758.15,-17635.85 -30758.15,-17765.37 -30729.22,-17794.31 C20.2@-30674.88,-17794.31 ; U5.23@-30978,-17406 -30978,-17587.58 -30957.58,-17608 ; U5.25@-30934.75,-17410.47 -30934.75,-17381.63 -30925.57,-17372.45 -30791.61,-17372.45 ; C22.2@-30908.08,-16451.01 -30908.26,-16467.74 -30909.24,-16466.76 C22.2@-30908,-16465.53 ; -30900,-17922 -30900,-17816 -30888.17,-17804.17 -30980.49,-17711.85 -30980.49,-17630.91 -30957.58,-17608 ; -30888,-17804 U5.42@-30860,-17804 ; U5.32@-30859.94,-17607.32 -30956.9,-17607.32 -30957.58,-17608 ; -30797.33,-17372.51 -30639.58,-17372.51 -30605.86,-17406.23 -30605.86,-17534.86 C16.2@-30607.35,-17536.35
  other v1: -33614.33,-15145.22 -32622.93,-15121.44
GPB0: U1.PA45
GPB1: LCD.11 U1.PA46 | length 1701.6
  Top Layer w10: v1(-33432,-15308) -33307.19,-15183.19 LCD.11@-33307.19,-15159.43
  Bottom Layer w10: U1.PA46@-33655.53,-16641.32 -33658.22,-16641.32 -33658.22,-16635.19 -33744.71,-16548.71 -33744.71,-15860.71 -33444,-15560 -33444,-15320 v1(-33432,-15308)
I2CSCL: Camera.2 U1.PA56 | length 2057
  Top Layer w10: U1.PA56@-33655.53,-16247.62 -33655.53,-16222.08 -33624.51,-16191.06 -33444.91,-16191.06 -33401.3,-16234.67 -32495.75,-16234.67 -32414.82,-16153.74 -32414.82,-16150.95 -32414.72,-16150.85 -32414.72,-15600.01 -32294.35,-15479.65 Camera.2@-32296,-15478
I2CSDA: Camera.1 U1.PA55 | length 2117.5
  Bottom Layer w10: U1.PA55@-33576.79,-16247.62 -33427.62,-16396.79 -32406.35,-16396.79 -32336.76,-16327.19 -32336.76,-15797.7 -32294,-15754.94 Camera.1@-32294,-15558
I2SLRCK: U1.PA40
I2SSCLK: U1.PA41
I2SSD0: U1.PA44
I2SSDI: U1.PA43
L3CLOCK: U1.PA39
L3DATA: U1.PA38
L3MODE: U1.PA37
LADDR0: U1.PC13
LADDR1: U1.PC15
LADDR2: U1.PC16 U5.92 | length 1279.2
  Bottom Layer w10: U1.PC16@-31726.39,-16798.8 -31765.06,-16837.47 -31819.52,-16837.47 -31850.03,-16867.98 -31850.03,-17626.33 -31849,-17627.36 -31657.38,-17627.36 -31638.04,-17646.69 U5.92@-31489.87,-17646.69
LADDR3: U1.PC17
LADDR4: U1.PC18
LADDR5: U1.PC19
LADDR6: U1.PC20
LADDR7: U1.PC21
LADDR8: U1.PC22
LADDR9: U1.PC23
LADDR10: U1.PC24
LADDR11: U1.PC25
LADDR12: U1.PC26
LADDR13: U1.PC27
LADDR14: U1.PC28
LADDR15: U1.PC29
LADDR16: U1.PC30
LADDR17: U1.PC31
LADDR18: U1.PC32
LADDR19: U1.PC33
LADDR20: U1.PC34
LADDR21: U1.PC35
LADDR22: U1.PC36
LADDR23: U1.PC37
LADDR24: U1.PC38
LCD_PWR: LCD.12 U1.PB29 | length 1878.1
  Top Layer w10: v1(-33288,-15430) LCD.12@-33288,-15364 ; v1(-33072.14,-15881.48) -33053.69,-15898.38 -33045.08,-15906.99 -33045.08,-16143.58 -32997.92,-16190.74 -32555.67,-16190.74 -32533.48,-16168.55 U1.PB29@-32533.48,-16109.83
  Bottom Layer w10: v1(-33288,-15430) -33288,-15618 -33487.66,-15817.66 -33487.66,-15863.59 -33469.77,-15881.48 -33104.28,-15881.48 v1(-33072.14,-15881.48)
LCDVF0: R16.1 U1.PA27 | length 1078.4
  Top Layer w10: v1@-34020,-17852 -33741.59,-17573.59 -33741.59,-17432.56 -33698.47,-17389.44 -33614.54,-17389.44 -33576.79,-17351.69 U1.PA27@-33576.79,-17349.98
  Bottom Layer w10: R16.1@-34292.55,-17853.76 -34292.55,-17900.61 -34280.88,-17912.27 -34133.76,-17912.27 -34079.39,-17857.9 v1@-34023.1,-17857.9
  other v1: -34024,-17858
LDATA0: U1.PC39 U5.6 | length 939.9
  Top Layer w10: U1.PC39@-31805.13,-17743.68 -31839.59,-17743.68 -31870.84,-17712.43 -31870.84,-17501.76 -31839.09,-17470 -31380.06,-17470 -31352.01,-17498.06 v1(-31352.01,-17500.23)
  Bottom Layer w10: v1@-31350.15,-17499.75 -31340,-17489.59 -31340,-17475.17 -31312.7,-17447.87 U5.6@-31312.7,-17410.47
LDATA1: U1.PC40 U5.7 | length 714.2
  Top Layer w10: U1.PC40@-31726.39,-17743.68 -31713.08,-17743.68 -31679.5,-17710.11 -31679.5,-17550.38 -31657.35,-17528.23 -31324.23,-17528.23 v1@-31324,-17528
  Bottom Layer w10: v1(-31322,-17528) -31322,-17483.54 -31293.1,-17454.65 U5.7@-31293.1,-17411.1
LDATA2: U1.PC41 U5.8 | length 891.5
  Top Layer w10: U1.PC41@-31805.13,-17822.42 -31766.42,-17783.71 -31686.58,-17783.71 -31656.42,-17753.56 -31656.42,-17569.66 -31646.76,-17560 -31312,-17560 -31292,-17540 -31292,-17486 -31292.08,-17486.08 v1(-31292.08,-17493.62)
  Bottom Layer w10: v1(-31292.08,-17493.62) v1@-31292,-17493.54 ; v1@-31291.71,-17495.42 -31291.71,-17480.66 -31273.23,-17462.17 U5.8@-31273.23,-17411.23
LDATA3: U1.PC42 U5.9 | length 836
  Top Layer w10: U1.PC42@-31726.39,-17822.42 -31658.78,-17822.42 -31636.38,-17800.03 -31636.38,-17592.66 -31625.72,-17582 -31304,-17582 -31262,-17540 v1(-31262,-17528)
  Bottom Layer w10: v1(-31262,-17528) -31262,-17476.4 -31253.72,-17468.13 U5.9@-31253.72,-17410.28
LDATA4: U1.PC43 U5.10 | length 984.5
  Top Layer w10: U1.PC43@-31805.13,-17901.17 -31766.71,-17862.74 -31651.87,-17862.74 -31613.3,-17824.18 -31613.3,-17606.12 -31296.11,-17606.12 -31232,-17542 v1@-31232,-17484
  Bottom Layer w10: U5.10@-31234,-17410 -31234,-17484 v1(-31232,-17486)
LDATA5: U1.PC44 U5.11 | length 938.5
  Top Layer w10: U1.PC44@-31726.39,-17901.17 -31633.67,-17901.17 -31590.83,-17858.32 -31590.83,-17637.3 -31583.86,-17630.33 ; -31582.37,-17628.84 -31286.08,-17628.84 -31202,-17544.76 v1(-31202,-17528)
  Bottom Layer w10: U5.11@-31214.17,-17410.64 -31214.17,-17461.83 -31202,-17474 v1(-31202,-17528)
LDATA6: U1.PC45 U5.12 | length 1093.9
  Top Layer w10: U1.PC45@-31805.13,-17979.9 -31766.44,-17941.22 -31613.4,-17941.22 -31568.96,-17896.78 -31568.96,-17666.93 -31558.09,-17656.06 -31276.66,-17656.06 -31174,-17553.4 v1(-31174,-17486)
  Bottom Layer w10: U5.12@-31194.59,-17410.47 -31194.59,-17445.41 -31174,-17466 v1(-31174,-17486)
LDATA7: U1.PC46 U5.13 | length 1069.4
  Top Layer w10: U1.PC46@-31726.39,-17979.9 -31598.85,-17979.9 -31548.92,-17929.98 -31548.92,-17685.58 -31542.89,-17679.56 -31252.28,-17679.56 -31144,-17571.27 v1@-31144,-17526
  Bottom Layer w10: U5.13@-31174.96,-17411.51 -31174.96,-17439.04 -31144,-17470 v1(-31144,-17528)
LDATA8: U1.PC47 U5.89 | length 619.8
  Bottom Layer w10: U1.PC47@-31805.13,-18058.65 -31765.71,-18019.22 -31701,-18019.22 -31678.68,-17996.9 -31678.68,-17726.57 -31657.86,-17705.75 U5.89@-31489.87,-17705.75
LDATA9: U1.PC48 U5.88 | length 528.8
  Bottom Layer w10: U1.PC48@-31726.39,-18058.65 -31709.31,-18058.65 -31653.83,-18003.17 -31653.83,-17739.84 -31639.43,-17725.43 U5.88@-31489.87,-17725.43
LDATA10: U1.PC49 U5.87 | length 638.3
  Bottom Layer w10: U1.PC49@-31805.13,-18137.38 -31766.02,-18098.27 -31697.67,-18098.27 -31632.3,-18032.9 -31632.3,-17758.78 -31618.64,-17745.12 U5.87@-31489.87,-17745.12
LDATA11: U1.PC50 U5.86 | length 554.8
  Bottom Layer w10: U1.PC50@-31726.39,-18137.38 -31688.91,-18137.38 -31613.7,-18062.18 -31613.7,-17782.29 -31596.22,-17764.8 U5.86@-31489.87,-17764.8
LDATA12: U1.PC51 U5.85 | length 654.9
  Bottom Layer w10: U1.PC51@-31805.13,-18216.12 -31765.07,-18176.06 -31685.31,-18176.06 -31593.43,-18084.18 -31593.43,-17809.62 -31568.29,-17784.49 U5.85@-31489.87,-17784.49
LDATA13: U1.PC52 U5.84 | length 571.4
  Bottom Layer w10: U1.PC52@-31726.39,-18216.12 -31683.6,-18216.12 -31575.43,-18107.95 -31575.43,-17827.83 -31551.59,-17804 -31551.42,-17804.17 U5.84@-31489.87,-17804.17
